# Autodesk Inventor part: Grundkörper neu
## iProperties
Created: 2008-02
Part Number: Grundkörper neu
Document SubType Name: Modeling
Designer: Benno
Manufacturer: Standard
Standards Organization: Custom
Author: Benno
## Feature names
1. Extrusion1
2. Fase1 [Chamfer]
3. Fase2 [Chamfer]
4. Extrusion2
5. Extrusion4
6. Extrusion5
7. Extrusion6
8. Extrusion7
9. Bohrung1 [Hole]
10. Extrusion8
11. Extrusion9
12. Bohrung3 [Hole]
13. Bohrung4 [Hole]
